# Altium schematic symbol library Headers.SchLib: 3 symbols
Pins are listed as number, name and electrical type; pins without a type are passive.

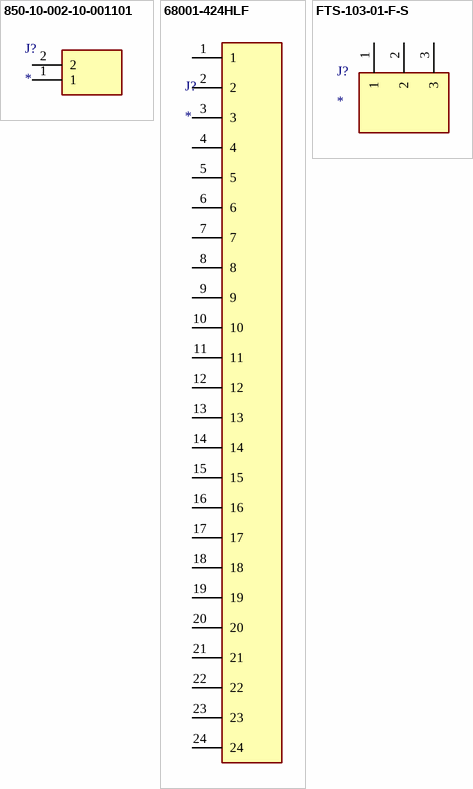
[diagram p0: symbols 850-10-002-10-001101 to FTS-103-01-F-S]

## 850-10-002-10-001101
designator J?
Connector; Manufacturer_Name: Preci-Dip; Manufacturer_Part_Number: 850-10-002-10-001101
footprint 8501000210001101
pins: 1, 2

## 68001-424HLF
designator J?
Connector; Manufacturer_Name: Amphenol Communications Solutions; Manufacturer_Part_Number: 68001-424HLF
footprint 68001424HLF
pins: 1, 2, 3, 4, 5, 6, 7, 8, 9, 10, 11, 12, 13, 14, 15, 16, 17, 18, 19, 20, 21, 22, 23, 24

## FTS-103-01-F-S
designator J?
Connector; Manufacturer_Name: SAMTEC; Manufacturer_Part_Number: FTS-103-01-F-S
footprint FTS10301FS
pins: 1, 2, 3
